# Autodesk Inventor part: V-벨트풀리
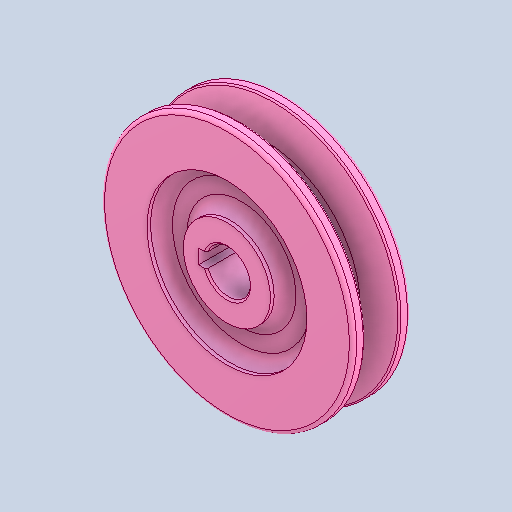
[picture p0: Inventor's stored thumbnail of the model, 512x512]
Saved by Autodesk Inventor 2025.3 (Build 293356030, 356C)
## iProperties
Created: 2025-08
Part Number: V-벨트풀리
Material: 강철, 연강
Document SubType Name: Modeling
Designer: user
Density: 7.86 g/cm^3
Appearance: 기본값
Sending System: Autodesk Inventor 2026
Preprocessor: ST-DEVELOPER v20.1
Author: jhkim
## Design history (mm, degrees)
sketch "스케치1"
  geometry: 1 further point
  constraints: 1 other
feature "Solid1"
node "솔리드1"
